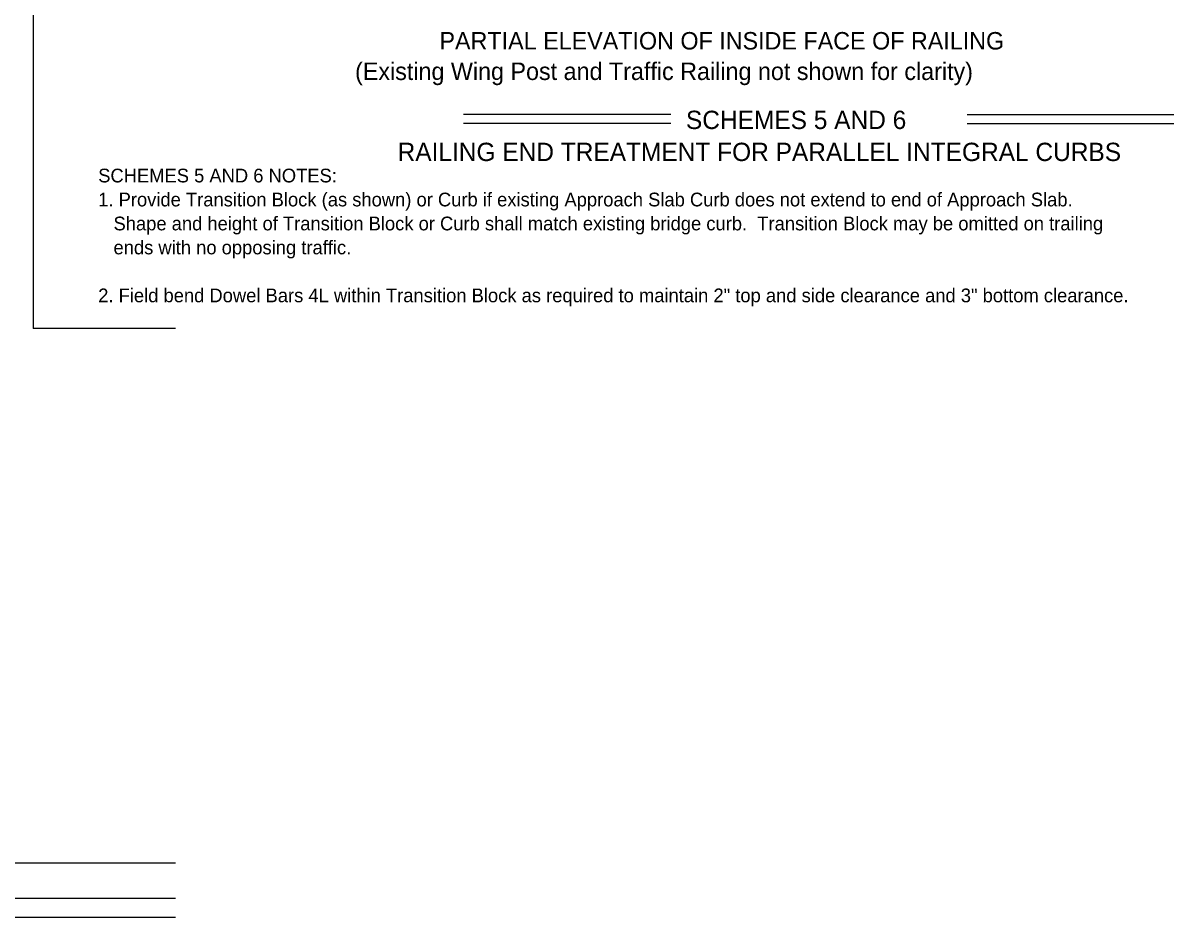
# Model space of a CAD drawing. Extents: x 21587 to 21656.3, y 56117.4 to 56157.3.
# Drawn here: x 21605.35 to 21622.25, y 56118.68 to 56131.8 of the extents above; entities that cross this region are included whole.
import ezdxf

# ---------------------------------------------------------------- set-up
doc = ezdxf.new("R2010")
doc.units = 0
doc.layers.add('Border', color=7, linetype='Continuous')
doc.layers.add('PlotBorder_dp', color=7, linetype='Continuous')

msp = doc.modelspace()

# ---------------------------------------------------------------- linework, layer by layer
at = {"layer": 'Border'}
for p, q in [((21607.59, 56119.465), (21586.978, 56119.465)), ((21607.59, 56118.949), (21586.978, 56118.949)), ((21586.978, 56118.676), (21607.59, 56118.676))]:
    msp.add_line(p, q, dxfattribs=at)
at = {"layer": 'PlotBorder_dp'}
for p, q in [((21605.502, 56153.256), (21605.502, 56127.317)), ((21614.863, 56130.46), (21611.821, 56130.46)), ((21619.217, 56130.46), (21622.254, 56130.46)), ((21614.863, 56130.327), (21611.821, 56130.327)), ((21619.217, 56130.327), (21622.254, 56130.327)), ((21607.59, 56127.317), (21605.502, 56127.317))]:
    msp.add_line(p, q, dxfattribs=at)

# ---------------------------------------------------------------- texts
for s, height, p in [('PARTIAL ELEVATION OF INSIDE FACE OF RAILING', 0.256, (21611.467, 56131.415)), ('(Existing Wing Post and Traffic Railing not shown for clarity)', 0.256, (21610.227, 56130.967)), ('SCHEMES 5 AND 6', 0.2688, (21615.087, 56130.247)), ('RAILING END TREATMENT FOR PARALLEL INTEGRAL CURBS', 0.2688, (21610.852, 56129.777)), ('SCHEMES 5 AND 6 NOTES:', 0.2016, (21606.455, 56129.463)), ('1. Provide Transition Block (as shown) or Curb if existing Approach Slab Curb does not extend to end of Approach Slab.  ', 0.2016, (21606.455, 56129.111)), ('   Shape and height of Transition Block or Curb shall match existing bridge curb.  Transition Block may be omitted on trailing ', 0.2016, (21606.455, 56128.759)), ('   ends with no opposing traffic.', 0.2016, (21606.455, 56128.407)), ('2. Field bend Dowel Bars 4L within Transition Block as required to maintain 2" top and side clearance and 3" bottom clearance.', 0.2016, (21606.455, 56127.703))]:
    msp.add_text(s, height=height, dxfattribs=at).set_placement(p)

doc.saveas('drawing.dxf')
